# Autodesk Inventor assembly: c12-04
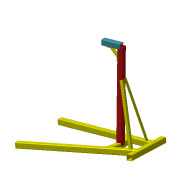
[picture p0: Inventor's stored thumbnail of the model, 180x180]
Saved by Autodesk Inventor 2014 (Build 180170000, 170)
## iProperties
Created: 2011-01
Part Number: c12-04
Document SubType Name: Assembly
Designer: Thom Tremblay
_SolveAssemblyDoc: Frame Generator Solve Assembly
_Version: 15.0.0
Author: Thom Tremblay
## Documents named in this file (3)
- C:\Inventor 2014 Essentials\Assemblies\Chapter 12\c12-04.iam
- C:\Inventor 2014 Essentials\Assemblies\Chapter 12\Frame\Frame c12-04.iam
- C:\Inventor 2014 Essentials\Parts\Chapter 12\c12-02.ipt
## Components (2 placed, 2 different names)
1. c12-02:1
2. Frame c12-04:1 [sub-assembly]
